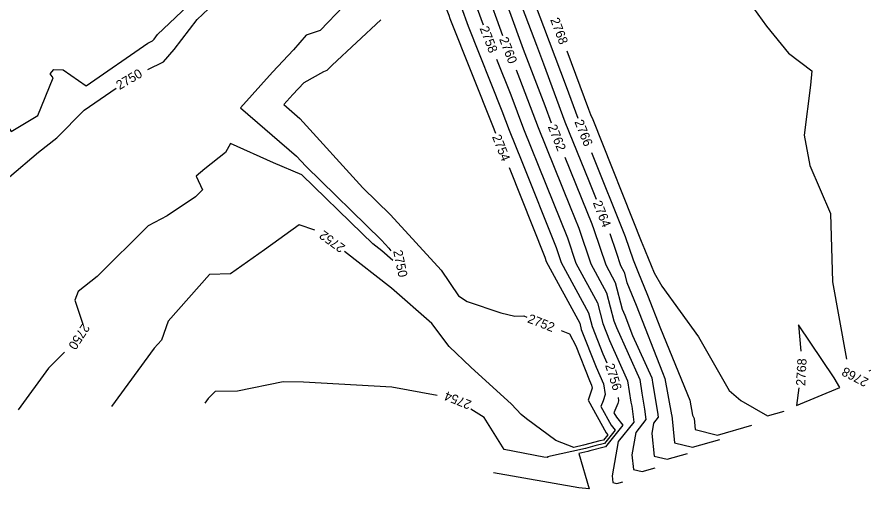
# Model space of a CAD drawing. Extents: x 1326424 to 1329294, y 1001359 to 1003823.
# Drawn here: x 1328782.8 to 1328967.7, y 1001477.8 to 1001580 of the extents above; entities that cross this region are included whole.
import ezdxf

# ---------------------------------------------------------------- set-up
doc = ezdxf.new("R2010")
doc.units = 0
doc.layers.add('Prop Rem of Exist Asph Pvmt', color=7, linetype='Continuous')
doc.layers.add('Scratch_Level_3', color=7, linetype='Continuous')

msp = doc.modelspace()

# ---------------------------------------------------------------- linework, layer by layer
at = {"layer": 'Prop Rem of Exist Asph Pvmt'}
for points in [[(1328852.42, 1001666.98), (1328857.73, 1001653.27), (1328860.47, 1001646.66), (1328861.79, 1001642.97), (1328865.5, 1001632.15), (1328869.9, 1001622.53), (1328871.71, 1001621.59), (1328872.86, 1001621.29), (1328874.86, 1001617.43), (1328877.49, 1001614.03), (1328877.51, 1001612.89), (1328881.53, 1001604.3), (1328883.67, 1001599.74), (1328884.42, 1001591.47), (1328884.61, 1001588.29), (1328883.9, 1001587.09), (1328884.35, 1001585.92), (1328887.93, 1001576.01)], [(1328890.84, 1001568.56), (1328891.57, 1001566.71), (1328895.6, 1001556.1), (1328902.54, 1001538.93), (1328904.39, 1001534.29), (1328907.02, 1001526.53), (1328910.39, 1001520.32), (1328911.98, 1001514.24), (1328912.54, 1001512.81), (1328917.59, 1001501.55), (1328918.06, 1001498.52), (1328918.67, 1001495.08), (1328918.95, 1001492.83), (1328916.73, 1001490.07), (1328915.92, 1001485.22), (1328916.26, 1001482.05), (1328918.1, 1001481.61), (1328920.94, 1001482.41)]]:
    msp.add_lwpolyline(points, dxfattribs=at)
at = {"layer": 'Scratch_Level_3'}
for points in [[(1328849.25, 1001667.92), (1328849.44, 1001667.36), (1328856.76, 1001648.47), (1328857.88, 1001645.78), (1328858.41, 1001644.28), (1328864.22, 1001627.36), (1328866.67, 1001622), (1328870.23, 1001620.15), (1328872.49, 1001619.56), (1328875.79, 1001613.18), (1328876.09, 1001613.07), (1328876.29, 1001612.56), (1328877.69, 1001608.98), (1328881, 1001601.9), (1328881.61, 1001600.6), (1328881.82, 1001598.23), (1328882.33, 1001590.13), (1328880.5, 1001587.08), (1328881.65, 1001584.08), (1328883.72, 1001578.34)], [(1328867.81, 1001650.42), (1328868.27, 1001649.3), (1328870.02, 1001644.4), (1328870.46, 1001643.27), (1328874.19, 1001634.86), (1328879.69, 1001621.52), (1328882.7, 1001617.63), (1328882.83, 1001612.15), (1328883.13, 1001611.5), (1328889.84, 1001597.18), (1328890.21, 1001593.12), (1328894.58, 1001583.74), (1328896.79, 1001577.93), (1328901.65, 1001564.97), (1328904.19, 1001558.12), (1328904.2, 1001558.09)], [(1328862.39, 1001649.18), (1328863.07, 1001647.54), (1328865.17, 1001641.67), (1328866.79, 1001636.95), (1328873.13, 1001623.06), (1328873.19, 1001623.03), (1328873.23, 1001623.02), (1328873.3, 1001622.89), (1328879.23, 1001615.23), (1328879.29, 1001612.64), (1328882.06, 1001606.7), (1328885.72, 1001598.89), (1328886.71, 1001588.01), (1328887.37, 1001586.6), (1328889.42, 1001581.19), (1328892.36, 1001573.04), (1328893.48, 1001570.23), (1328897.03, 1001560.87), (1328898.44, 1001557.07)], [(1328871.96, 1001632.81), (1328873.71, 1001628.86), (1328876.41, 1001622.32), (1328880.96, 1001616.43), (1328881.06, 1001612.39), (1328882.6, 1001609.1), (1328887.78, 1001598.03), (1328888.46, 1001590.56), (1328890.98, 1001585.17), (1328895.23, 1001573.95), (1328896.76, 1001569.88), (1328901.42, 1001557.31), (1328906.57, 1001544.54), (1328908.17, 1001540.56)], [(1328845.08, 1001609), (1328858.56, 1001619.12), (1328858.93, 1001619.29), (1328859.48, 1001619.36), (1328863.72, 1001619.11), (1328867.26, 1001617.26), (1328871.75, 1001616.1), (1328872.74, 1001614.18), (1328875.93, 1001612.94), (1328878.11, 1001607.41), (1328880.6, 1001601.02), (1328878.74, 1001599.19), (1328877.51, 1001597.73), (1328877.75, 1001593.82), (1328873.71, 1001587.05), (1328876.25, 1001580.41), (1328876.5, 1001579.73), (1328885.85, 1001556.17), (1328886.22, 1001555.21), (1328886.36, 1001554.85)], [(1328811.15, 1001568.66), (1328814.48, 1001570.33), (1328816.83, 1001573), (1328821.79, 1001579.51), (1328827.94, 1001585.36), (1328839.82, 1001597.03), (1328843.1, 1001599.84), (1328848.63, 1001604.2), (1328853.32, 1001607.59), (1328855.92, 1001609.54), (1328861.5, 1001611.97), (1328863.19, 1001612.17), (1328863.09, 1001611.46), (1328866.15, 1001613.81), (1328869.72, 1001614.17), (1328871.18, 1001614.27), (1328874.56, 1001613.29), (1328875.77, 1001612.82), (1328879.94, 1001602.26), (1328880.38, 1001601.13), (1328877.38, 1001598.19)], [(1328879.69, 1001597.68), (1328880.04, 1001591.97), (1328877.1, 1001587.07), (1328878.95, 1001582.25), (1328880.47, 1001578.06), (1328887.76, 1001559.68), (1328889.34, 1001555.51), (1328892.08, 1001548.76), (1328899.49, 1001530.08), (1328900.58, 1001526.87), (1328906.54, 1001515.92), (1328907.3, 1001512.98), (1328909.63, 1001507.06), (1328910.49, 1001505.16)], [(1328931.04, 1001595.01), (1328931.6, 1001593.81), (1328931.95, 1001592.92), (1328932.06, 1001592.77), (1328935.91, 1001588.71), (1328936.26, 1001587.46), (1328942.2, 1001581.92), (1328945.06, 1001578.07), (1328949.83, 1001572.17), (1328954.85, 1001568.36), (1328954.6, 1001565.23), (1328953.2, 1001554.4), (1328954.44, 1001547.84), (1328958.87, 1001537.49), (1328959.32, 1001522.67), (1328962.25, 1001506.72), (1328962.39, 1001505.94)], [(1328871.08, 1001594.56), (1328868.97, 1001593.79), (1328868.1, 1001593.35), (1328866.93, 1001592.6), (1328864.64, 1001589.96), (1328863.72, 1001588.74), (1328862.96, 1001588.91), (1328860.63, 1001588.37), (1328858.51, 1001588.48), (1328855.66, 1001586.06), (1328854.03, 1001584.94), (1328853.52, 1001582.42), (1328848.44, 1001577.11), (1328845.38, 1001576.1), (1328842.62, 1001572.89), (1328838.1, 1001568.05), (1328831.17, 1001560.35), (1328843.32, 1001549.86), (1328845.29, 1001547.69), (1328861.73, 1001531.66), (1328863.32, 1001529.93), (1328863.7, 1001529.36)], [(1328750.56, 1001584.48), (1328755.91, 1001583.74), (1328764.13, 1001577.63), (1328775.9, 1001563.33), (1328779.13, 1001559.4), (1328781.51, 1001555.19), (1328787.33, 1001558.67), (1328790.64, 1001566.87), (1328789.98, 1001567.68), (1328790.77, 1001568.62), (1328792.81, 1001568.58), (1328797.74, 1001565.09), (1328811.08, 1001574.32), (1328812.14, 1001574.85), (1328812.49, 1001575.25), (1328813.22, 1001576.2), (1328821.04, 1001583.65)], [(1328861.57, 1001579.43), (1328851.02, 1001569.6), (1328849.88, 1001568.41), (1328849.15, 1001568.18), (1328844.91, 1001565.77), (1328842.53, 1001563.22), (1328840.56, 1001561.04), (1328844, 1001558.07), (1328857.67, 1001542.99), (1328863.64, 1001537.17), (1328874.65, 1001525.2), (1328878.35, 1001519.67), (1328880.25, 1001518.38), (1328887.56, 1001515.93), (1328890.53, 1001515.23), (1328892.53, 1001515.29), (1328893.14, 1001515.04)], [(1328901.79, 1001572.72), (1328906.54, 1001560.06), (1328906.95, 1001558.93), (1328907.42, 1001557.79), (1328918.09, 1001531.13), (1328918.15, 1001530.95), (1328920.71, 1001524.58), (1328922.36, 1001521.75), (1328930.31, 1001510.76), (1328936.96, 1001499.13), (1328939.47, 1001496.94), (1328945.25, 1001493.63), (1328948.89, 1001494.65)], [(1328886.62, 1001570.88), (1328889.67, 1001563.2), (1328892.47, 1001555.8), (1328897.31, 1001543.84), (1328901.94, 1001532.18), (1328903.8, 1001526.7), (1328908.46, 1001518.12), (1328909.64, 1001513.61), (1328911.09, 1001509.94), (1328914.99, 1001501.24), (1328915.71, 1001496.62), (1328915.86, 1001495.74), (1328916.3, 1001492.3), (1328912.9, 1001488.07), (1328911.65, 1001480.64), (1328911.8, 1001479.18), (1328912.65, 1001478.98), (1328913.95, 1001479.35)], [(1328725.18, 1001504.57), (1328734.81, 1001508.23), (1328740.35, 1001511.85), (1328743.34, 1001514.11), (1328750.69, 1001520.2), (1328751.95, 1001521.26), (1328758.22, 1001526.48), (1328769.78, 1001537.61), (1328774.4, 1001540.88), (1328774.69, 1001541.15), (1328781.16, 1001545.4), (1328787.46, 1001550.78), (1328791.45, 1001553.88), (1328797.3, 1001559.81), (1328804.26, 1001564.63)], [(1328864.13, 1001527.29), (1328861.76, 1001529.36), (1328859.83, 1001530.87), (1328857.53, 1001533.11), (1328844.46, 1001545.86), (1328838.35, 1001548.46), (1328829.01, 1001552.59), (1328827.94, 1001550.69), (1328823.47, 1001547.13), (1328821.57, 1001545.54), (1328822.96, 1001542.58), (1328821.4, 1001541.06), (1328815.31, 1001536.98), (1328811.2, 1001534.76), (1328800.17, 1001523.81), (1328796.06, 1001520.59), (1328795.3, 1001518.73), (1328797.02, 1001513.52)], [(1328907.19, 1001550.68), (1328914.47, 1001532.49), (1328916.19, 1001527.45), (1328917.21, 1001524.89), (1328919.3, 1001519.77), (1328922.12, 1001512.54), (1328928.46, 1001497.04), (1328929.05, 1001493.81), (1328929.36, 1001493.08), (1328929.61, 1001490.66), (1328934.45, 1001489.48), (1328941.9, 1001491.59)], [(1328901.41, 1001549.65), (1328906.15, 1001537.91), (1328907.23, 1001535.22), (1328907.64, 1001534.02), (1328910.24, 1001526.35), (1328912.32, 1001522.53), (1328913.83, 1001516.74), (1328914.36, 1001515.43), (1328916.06, 1001511.08), (1328920.2, 1001501.86), (1328920.42, 1001500.42), (1328921.47, 1001494.42), (1328921.61, 1001493.37), (1328920.57, 1001492.08), (1328920.19, 1001489.81), (1328920.71, 1001484.92), (1328923.55, 1001484.23), (1328927.92, 1001485.47)], [(1328889.32, 1001547.42), (1328897.04, 1001527.98), (1328897.36, 1001527.04), (1328904.61, 1001513.71), (1328904.96, 1001512.35), (1328908.18, 1001504.19), (1328909.79, 1001500.61), (1328910.15, 1001498.24), (1328909.71, 1001496.9), (1328909.21, 1001495.7), (1328911.44, 1001491.66), (1328912.32, 1001490.56), (1328909.99, 1001487.66), (1328907.91, 1001487.13), (1328905.89, 1001486.59), (1328897.65, 1001484.77), (1328897.69, 1001484.63), (1328896.87, 1001484.73), (1328888.29, 1001486.37), (1328883.9, 1001493.32), (1328881.05, 1001495.1)], [(1328847.24, 1001533.86), (1328843.86, 1001535.03), (1328836.36, 1001529.59), (1328829.01, 1001524.39), (1328824.5, 1001524.24), (1328815.53, 1001514.14), (1328814.09, 1001510), (1328812.48, 1001508.33), (1328803.24, 1001495.68)], [(1328911.1, 1001533.11), (1328912.47, 1001529.08), (1328913.46, 1001526.18), (1328914.25, 1001524.73), (1328914.82, 1001522.54), (1328916.83, 1001517.6), (1328922.52, 1001503.03), (1328923.06, 1001501.72), (1328924.49, 1001493.83), (1328924.53, 1001493.75), (1328925.16, 1001487.79), (1328929, 1001486.86), (1328934.91, 1001488.53)], [(1328900.58, 1001512.11), (1328902.41, 1001511.4), (1328903.76, 1001508.83), (1328906.73, 1001501.32), (1328907.18, 1001500.3), (1328907.29, 1001499.62), (1328906.57, 1001497.47), (1328906.41, 1001497.07), (1328910.35, 1001489.94), (1328910.69, 1001489.52), (1328909.79, 1001488.41), (1328909, 1001488.2), (1328905.43, 1001487.26), (1328903.31, 1001486.79), (1328899.42, 1001488.34), (1328893.1, 1001493.02), (1328891.93, 1001493.95), (1328889.85, 1001496.2), (1328881.01, 1001504.19), (1328876.37, 1001508.68), (1328872.57, 1001513.65), (1328863.85, 1001521.26), (1328853.66, 1001529.26)], [(1328960.91, 1001499.75), (1328959.67, 1001501.85), (1328952, 1001513.39), (1328952.49, 1001507.68)], [(1328793.1, 1001507.45), (1328789.61, 1001503.97), (1328783.02, 1001494.94)], [(1328967.29, 1001503.4), (1328967.65, 1001503.56)], [(1328873.75, 1001498.02), (1328863.96, 1001499.87), (1328844.84, 1001500.97), (1328840.43, 1001500.99), (1328830.55, 1001498.98), (1328825.66, 1001498.94), (1328824.2, 1001497.42), (1328823.47, 1001496.42)], [(1328952.06, 1001499.74), (1328951.51, 1001495.91), (1328960.91, 1001499.75)], [(1328912.9, 1001497.61), (1328913.02, 1001496.87), (1328912.84, 1001496.34), (1328912.01, 1001494.33), (1328912.54, 1001493.38), (1328913.96, 1001491.61), (1328910.18, 1001486.91), (1328906.82, 1001486.05), (1328906.34, 1001485.92), (1328904.4, 1001485.5), (1328906.65, 1001477.82), (1328904.43, 1001478.07), (1328885.94, 1001481.28)]]:
    msp.add_lwpolyline(points, dxfattribs=at)

# ---------------------------------------------------------------- texts
at = {"layer": 'Prop Rem of Exist Asph Pvmt'}
msp.add_text('2760', height=2, rotation=291.345, dxfattribs=at).set_placement((1328887.13, 1001575.24))
at = {"layer": 'Scratch_Level_3'}
for s, rotation, p in [('2768', 290.5506, (1328898.2, 1001579.45)), ('2758', 291.1899, (1328882.91, 1001577.58)), ('2750', 30.3184, (1328804.99, 1001564.19)), ('2766', 291.9766, (1328903.43, 1001557.32)), ('2762', 291.864, (1328897.66, 1001556.29)), ('2754', 291.7109, (1328885.59, 1001554.1)), ('2764', 291.519, (1328907.42, 1001539.79)), ('2752', 144.3461, (1328854.01, 1001530.45)), ('2750', 281.6906, (1328864.22, 1001529.34)), ('2752', 338.5388, (1328893.15, 1001513.93)), ('2750', 237.1782, (1328797.03, 1001513.84)), ('2768', 86.885, (1328953.42, 1001500.08)), ('2756', 287.7381, (1328910.08, 1001504.62)), ('2768', 152.6214, (1328967.31, 1001501.58)), ('2754', 158.1495, (1328881.35, 1001496.81))]:
    msp.add_text(s, height=2, rotation=rotation, dxfattribs=at).set_placement(p)

doc.saveas('drawing.dxf')
